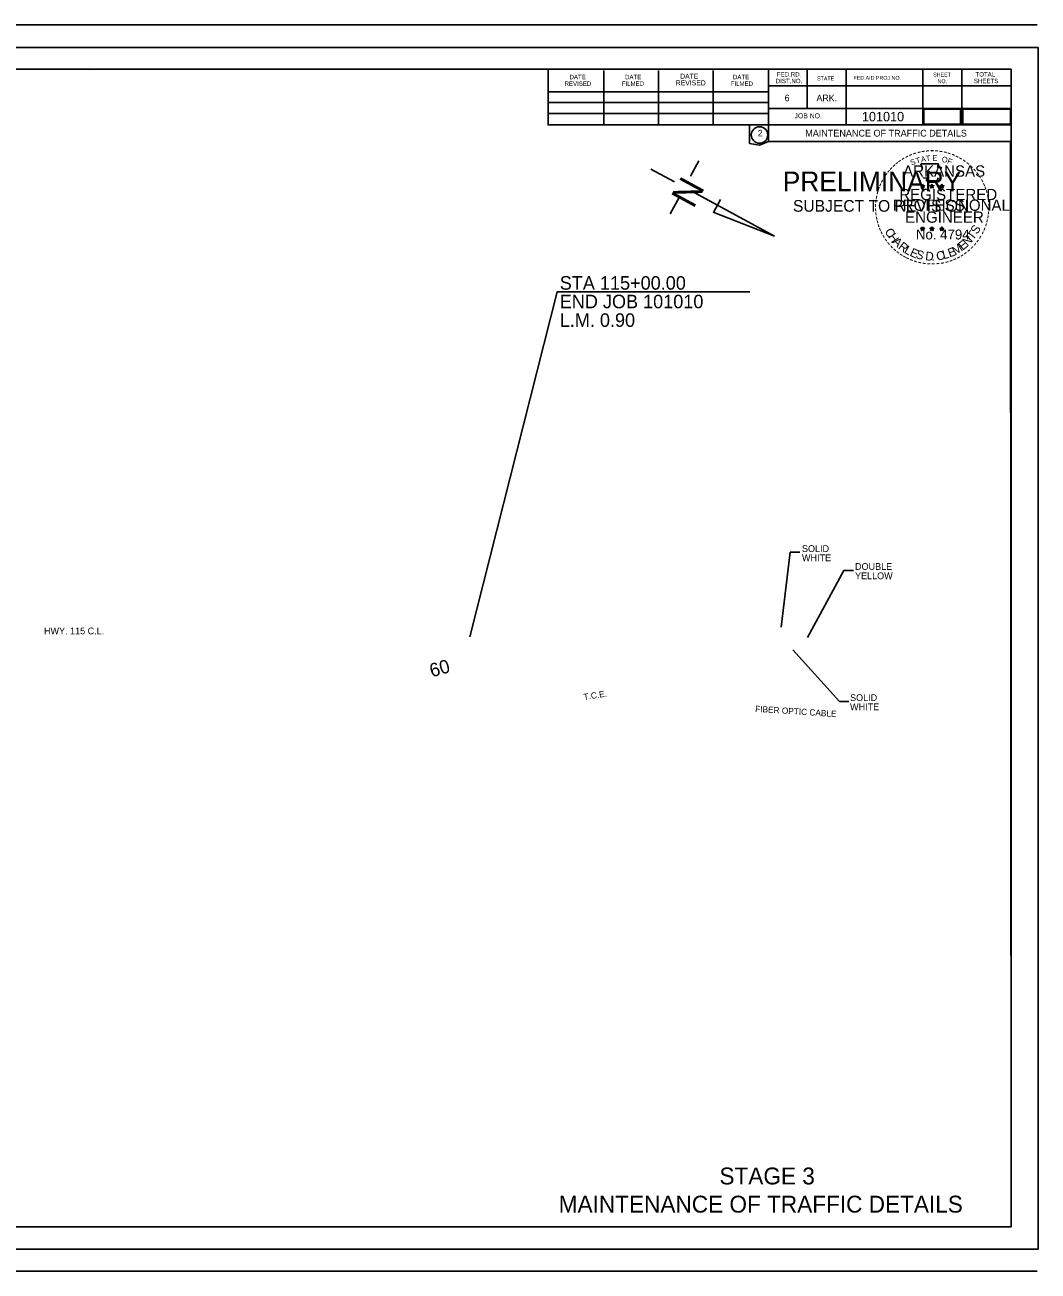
# Model space of a CAD drawing. Extents: x 9844 to 11605, y 9961 to 11312.
# Drawn here: x 10705 to 11605, y 9961 to 11067 of the extents above; entities that cross this region are included whole.
import ezdxf

# ---------------------------------------------------------------- set-up
doc = ezdxf.new("R2010")
doc.units = 0
for name, color, linetype in [('C-PSVP', 7, 'Continuous'), ('GREEN_TXT', 7, 'Continuous'), ('R_Border Notes', 7, 'Continuous'), ('R_Horz Alg', 7, 'Continuous'), ('R_Temp Const Easement Annot', 7, 'Continuous'), ('S_FIBER_OPTIC_CABLE_ANNOT', 7, 'Continuous'), ('SEAL-INFO', 7, 'Continuous'), ('SIGNATURE', 7, 'Continuous'), ('STA Text', 7, 'Continuous'), ('Stage 2', 7, 'Continuous'), ('TEXT', 7, 'Continuous'), ('Tracking', 7, 'Continuous'), ('White Markings DETOUR', 7, 'Continuous')]:
    doc.layers.add(name, color=color, linetype=linetype)

msp = doc.modelspace()

# ---------------------------------------------------------------- linework, layer by layer
for p, q in [((11303.5, 10946.1), (11296.1, 10932.5)), ((11260.8, 10938.8), (11281.8, 10927.4)), ((11299.2, 10918), (11370.7, 10879.2)), ((11285.8, 10913.6), (11278, 10899.1)), ((11322.6, 10911.7), (11316.4, 10900.3)), ((11370.7, 10879.2), (11316, 10900.6))]:
    msp.add_line(p, q)
at = {"layer": 'C-PSVP'}
for p, q in [((11500.3, 10924), (11502.1, 10923.5)), ((11500.3, 10924), (11501.6, 10923.8)), ((11500.3, 10924), (11501.5, 10923.4)), ((11501, 10922), (11502.1, 10923.5)), ((11501, 10922), (11501.6, 10923.2)), ((11501, 10922), (11502, 10923.1)), ((11502.1, 10925.3), (11501.8, 10924.1)), ((11503.1, 10922), (11502, 10923.1)), ((11502.1, 10923.5), (11502.1, 10925.3)), ((11502.1, 10925.3), (11502.3, 10924.1)), ((11503.8, 10924), (11502.1, 10923.5)), ((11503.1, 10922), (11502.1, 10923.5)), ((11503.8, 10924), (11502.4, 10923.8)), ((11503.1, 10922), (11502.4, 10923.5)), ((11503.8, 10924), (11502.8, 10923.5)), ((11508.7, 10924), (11510.4, 10923.5)), ((11508.7, 10924), (11509.9, 10923.8)), ((11508.7, 10924), (11509.8, 10923.4)), ((11509.3, 10922), (11510.4, 10923.5)), ((11509.3, 10922), (11510, 10923.2)), ((11509.3, 10922), (11510.4, 10923.1)), ((11510.4, 10925.3), (11510.2, 10924.1)), ((11510.4, 10923.5), (11510.4, 10925.3)), ((11510.4, 10925.3), (11510.6, 10924.1)), ((11512.1, 10924), (11510.4, 10923.5)), ((11511.5, 10922), (11510.4, 10923.5)), ((11511.5, 10922), (11510.4, 10923.1)), ((11512.1, 10924), (11510.7, 10923.8)), ((11511.5, 10922), (11510.8, 10923.5)), ((11512.1, 10924), (11511.1, 10923.5)), ((11517.5, 10924), (11519.2, 10923.4)), ((11517.5, 10924), (11518.7, 10923.8)), ((11517.5, 10924), (11518.7, 10923.4)), ((11518.1, 10921.9), (11519.2, 10923.4)), ((11518.1, 10921.9), (11518.8, 10923.2)), ((11518.1, 10921.9), (11519.2, 10923)), ((11519.2, 10925.3), (11519, 10924)), ((11519.2, 10923.4), (11519.2, 10925.3)), ((11519.2, 10925.3), (11519.5, 10924)), ((11521, 10924), (11519.2, 10923.4)), ((11520.3, 10921.9), (11519.2, 10923.4)), ((11520.3, 10921.9), (11519.2, 10923)), ((11521, 10924), (11519.5, 10923.7)), ((11520.3, 10921.9), (11519.6, 10923.4)), ((11521, 10924), (11519.9, 10923.5)), ((11500.3, 10886.2), (11502, 10885.6)), ((11500.3, 10886.2), (11501.6, 10886)), ((11500.3, 10886.2), (11501.5, 10885.6)), ((11501, 10884.1), (11502, 10885.6)), ((11501, 10884.1), (11501.6, 10885.4)), ((11501, 10884.1), (11502, 10885.2)), ((11502, 10887.4), (11501.8, 10886.2)), ((11502, 10885.6), (11502, 10887.4)), ((11502, 10887.4), (11502.3, 10886.2)), ((11503.8, 10886.2), (11502, 10885.6)), ((11503.1, 10884.1), (11502, 10885.6)), ((11503.1, 10884.1), (11502, 10885.2)), ((11503.8, 10886.2), (11502.3, 10885.9)), ((11503.1, 10884.1), (11502.4, 10885.6)), ((11503.8, 10886.2), (11502.7, 10885.7)), ((11508.6, 10886.2), (11510.4, 10885.6)), ((11508.6, 10886.2), (11509.9, 10886)), ((11508.6, 10886.2), (11509.8, 10885.6)), ((11509.3, 10884.1), (11510.4, 10885.6)), ((11509.3, 10884.1), (11509.9, 10885.4)), ((11509.3, 10884.1), (11510.4, 10885.2)), ((11510.4, 10887.4), (11510.2, 10886.2)), ((11510.4, 10885.6), (11510.4, 10887.4)), ((11510.4, 10887.4), (11510.6, 10886.2)), ((11512.1, 10886.2), (11510.4, 10885.6)), ((11511.4, 10884.1), (11510.4, 10885.6)), ((11511.4, 10884.1), (11510.4, 10885.2)), ((11512.1, 10886.2), (11510.7, 10885.9)), ((11511.4, 10884.1), (11510.8, 10885.6)), ((11512.1, 10886.2), (11511.1, 10885.7)), ((11517.5, 10886.1), (11519.2, 10885.6)), ((11517.5, 10886.1), (11518.7, 10885.9)), ((11517.5, 10886.1), (11518.7, 10885.5)), ((11518.1, 10884.1), (11519.2, 10885.6)), ((11518.1, 10884.1), (11518.8, 10885.3)), ((11518.1, 10884.1), (11519.2, 10885.2)), ((11519.2, 10887.4), (11519, 10886.1)), ((11519.2, 10885.6), (11519.2, 10887.4)), ((11519.2, 10887.4), (11519.5, 10886.1)), ((11520.9, 10886.1), (11519.2, 10885.6)), ((11520.3, 10884.1), (11519.2, 10885.6)), ((11520.3, 10884.1), (11519.2, 10885.2)), ((11520.9, 10886.1), (11519.5, 10885.9)), ((11520.3, 10884.1), (11519.6, 10885.5)), ((11520.9, 10886.1), (11519.9, 10885.6))]:
    msp.add_line(p, q, dxfattribs=at)
for points in [[(11500.5, 10943.4), (11501.9, 10939.3)], [(11518.1, 10938.8), (11518.8, 10940.2), (11515.4, 10940.1), (11516.1, 10943.4), (11500.5, 10943.4)], [(11503, 10931.3), (11503, 10930.9), (11505.8, 10930.8), (11505.5, 10928.4), (11514.9, 10928.4), (11515.9, 10931.1)], [(11502.1, 10925.3), (11503.1, 10922), (11500.3, 10924), (11503.8, 10924), (11501, 10922), (11502.1, 10925.3)], [(11510.4, 10925.3), (11511.5, 10922), (11508.7, 10924), (11512.1, 10924), (11509.3, 10922), (11510.4, 10925.3)], [(11519.2, 10925.3), (11520.3, 10921.9), (11517.5, 10924), (11521, 10924), (11518.1, 10921.9), (11519.2, 10925.3)], [(11502, 10887.4), (11503.1, 10884.1), (11500.3, 10886.2), (11503.8, 10886.2), (11501, 10884.1), (11502, 10887.4)], [(11510.4, 10887.4), (11511.4, 10884.1), (11508.6, 10886.2), (11512.1, 10886.2), (11509.3, 10884.1), (11510.4, 10887.4)], [(11519.2, 10887.4), (11520.3, 10884.1), (11517.5, 10886.1), (11520.9, 10886.1), (11518.1, 10884.1), (11519.2, 10887.4)]]:
    msp.add_lwpolyline(points, dxfattribs=at)
for centre, radius in [((11502, 10923.5), 0.861), ((11502, 10923.5), 0.723), ((11502, 10923.5), 0.579), ((11502, 10923.5), 0.495), ((11502, 10923.5), 0.374), ((11502, 10923.5), 0.248), ((11502, 10923.5), 0.148), ((11510.4, 10923.5), 0.861), ((11510.4, 10923.5), 0.723), ((11510.4, 10923.5), 0.579), ((11510.4, 10923.5), 0.495), ((11510.4, 10923.5), 0.374), ((11510.4, 10923.5), 0.248), ((11510.4, 10923.5), 0.148), ((11519.2, 10923.4), 0.861), ((11519.2, 10923.4), 0.723), ((11519.2, 10923.4), 0.579), ((11519.2, 10923.4), 0.495), ((11519.2, 10923.4), 0.374), ((11519.2, 10923.4), 0.248), ((11519.2, 10923.4), 0.148), ((11502, 10885.6), 0.861), ((11502, 10885.6), 0.723), ((11502, 10885.6), 0.579), ((11502, 10885.6), 0.495), ((11502, 10885.6), 0.374), ((11502, 10885.6), 0.248), ((11502, 10885.6), 0.148), ((11510.4, 10885.6), 0.861), ((11510.4, 10885.6), 0.723), ((11510.4, 10885.6), 0.579), ((11510.4, 10885.6), 0.495), ((11510.4, 10885.6), 0.374), ((11510.4, 10885.6), 0.248), ((11510.4, 10885.6), 0.148), ((11519.2, 10885.6), 0.861), ((11519.2, 10885.6), 0.723), ((11519.2, 10885.6), 0.579), ((11519.2, 10885.6), 0.495), ((11519.2, 10885.6), 0.374), ((11519.2, 10885.6), 0.248), ((11519.2, 10885.6), 0.148)]:
    msp.add_circle(centre, radius, dxfattribs=at)
at = {"layer": 'GREEN_TXT'}
for p, q in [((11603.9, 11066.7), (9843.9, 11066.7)), ((10000, 11027.3), (11580.9, 11027.3)), ((10762.6, 11026), (10762.6, 11026)), ((10762.6, 11026), (10762.6, 11026)), ((11169.6, 10977.9), (11169.6, 11027.3)), ((11218.9, 10977.9), (11218.9, 11026.3)), ((11267.7, 10977.9), (11267.7, 11026.3)), ((11316.1, 10977.9), (11316.1, 11026.3)), ((11365.4, 11027.3), (11365.4, 10963.3)), ((11399.6, 11027.3), (11399.6, 10992.6)), ((11434.3, 11027.3), (11434.3, 10977.9)), ((11502.2, 11027.3), (11502.2, 10977.9)), ((11536.9, 11027.3), (11536.9, 10977.9)), ((11580.9, 10000), (11580.9, 11027.3)), ((11169.6, 11007.2), (11365.4, 11007.2)), ((11580.9, 11012.6), (11365.4, 11012.6)), ((11580.9, 11012.7), (11580.9, 11012.7)), ((11169.6, 10997.9), (11365.4, 10997.9)), ((11169.6, 10988.2), (11365.4, 10988.2)), ((11580.9, 10992.6), (11365.4, 10992.6)), ((11580.9, 10977.9), (11169.6, 10977.9)), ((11365.4, 10963.3), (11580.9, 10963.3)), ((11580.9, 10000), (10000, 10000)), ((9843.9, 9960.6), (11603.9, 9960.6))]:
    msp.add_line(p, q, dxfattribs=at)
msp.add_circle((11357.3, 10969), 7.33, dxfattribs=at)
at = {"layer": 'R_Horz Alg'}
msp.add_lwpolyline([(11537.7, 10978.6), (11580.1, 10978.6), (11580.1, 10991.9), (11537.7, 10991.9)], close=True, dxfattribs=at)
at = {"layer": 'SEAL-INFO'}
for points in [[(9938, 11046.8), (11604.7, 11046.8), (11604.7, 9980.1), (9938, 9980.1)], [(10000, 10000), (11580.9, 10000), (11580.3, 10963.3), (11365.4, 10963.3), (11357.3, 10959.9), (11348.5, 10961.4), (11348.3, 10977.9), (11169.6, 10977.9), (11169.6, 11027.3), (10000, 11027.3)], [(10000, 10000), (11580.9, 10000), (11580.3, 10963.3), (11365.4, 10963.3), (11357.3, 10959.9), (11348.5, 10961.4), (11348.3, 10977.9), (11169.6, 10977.9), (11169.6, 11027.3), (10000, 11027.3)], [(10000, 10000), (11580.9, 10000), (11580.3, 10963.3), (11365.4, 10963.3), (11357.3, 10959.9), (11348.5, 10961.4), (11348.3, 10977.9), (11169.6, 10977.9), (11169.6, 11027.3), (10000, 11027.3)], [(10000, 10000), (11580.9, 10000), (11580.3, 10963.3), (11365.4, 10963.3), (11357.3, 10959.9), (11348.5, 10961.4), (11348.3, 10977.9), (11169.6, 10977.9), (11169.6, 11027.3), (10000, 11027.3)]]:
    msp.add_lwpolyline(points, close=True, dxfattribs=at)
at = {"layer": 'STA Text'}
msp.add_lwpolyline([(11348.8, 10829.8), (11177.7, 10829.8), (11100, 10523.5)], dxfattribs=at)
at = {"layer": 'Stage 2'}
for points in [[(11393, 10598.7), (11384.6, 10598.7), (11376.4, 10532.1)], [(11440.7, 10582.5), (11432.3, 10582.5), (11400, 10523)], [(11387, 10512.1), (11428.3, 10466.3), (11436.6, 10466.3)]]:
    msp.add_lwpolyline(points, dxfattribs=at)
at = {"layer": 'White Markings DETOUR'}
msp.add_lwpolyline([(11503.2, 10978.6), (11535.9, 10978.6), (11535.9, 10991.9), (11503.2, 10991.9)], close=True, dxfattribs=at)

# ---------------------------------------------------------------- texts
msp.add_text('N', height=23.3, rotation=241.4896).set_placement((11288.7, 10933.8))
at = {"layer": 'C-PSVP'}
for s, height, rotation, p in [('-', 8, 28.7918, (11487.9, 10946.1)), ('-', 8, 24.3072, (11491.1, 10947.7)), ('-', 8, 19.1761, (11494.3, 10949.1)), ('-', 8, 13.6302, (11498, 10950.3)), ('-', 8, 10.2193, (11501.4, 10951.1)), ('T', 5, 6.0228, (11505.2, 10945.6)), ('-', 8, 5.8968, (11505, 10951.6)), ('-', 8, 0.1862, (11508.9, 10952)), ('E', 5, 0.8323, (11510.8, 10946.1)), ('-', 8, 357.743, (11512.5, 10951.9)), ('-', 8, 352.1617, (11516.2, 10951.6)), ('-', 8, 347.2049, (11519.8, 10951.1)), ('-', 8, 342.3362, (11523, 10950.3)), ('-', 8, 337.8551, (11526.7, 10949.2)), ('-', 8, 334.1211, (11529.8, 10947.8)), ('-', 8, 48.4231, (11475.3, 10935.9)), ('-', 8, 42.9622, (11477.5, 10938.3)), ('-', 8, 38.9507, (11479.7, 10940.4)), ('-', 8, 36.2317, (11482, 10942.3)), ('-', 8, 34.0636, (11484.9, 10944.3)), ('S', 5, 21.594, (11492.3, 10941.8)), ('T', 5, 16.4036, (11496.9, 10943.5)), ('A', 5, 11.2132, (11501, 10944.7)), ('O', 5, 350.4515, (11518.8, 10945.1)), ('F', 5, 340.0707, (11523.5, 10943.9)), ('-', 8, 329.6409, (11532.7, 10946.4)), ('-', 8, 325.8627, (11535.9, 10944.6)), ('-', 8, 320.5297, (11539, 10942.5)), ('-', 8, 315.5786, (11542, 10940)), ('-', 8, 62.8713, (11468, 10925)), ('-', 8, 58.0706, (11469.6, 10928)), ('-', 8, 54.2325, (11471.2, 10930.7)), ('-', 8, 50.6142, (11473.2, 10933.5)), ('-', 8, 309.8797, (11544.8, 10937.3)), ('-', 8, 306.6522, (11547.5, 10934.3)), ('-', 7, 303.6753, (11549.9, 10931.4)), ('-', 8, 299.6684, (11551.5, 10928.4)), ('-', 8, 75.461, (11464.6, 10915.2)), ('-', 8, 72.3945, (11465.6, 10918.8)), ('-', 8, 67.7743, (11466.7, 10921.9)), ('-', 8, 294.6628, (11553.1, 10925.3)), ('-', 8, 290.5728, (11554.4, 10922.5)), ('-', 8, 285.1233, (11555.6, 10919.6)), ('-', 8, 89.0622, (11463.4, 10904.7)), ('-', 8, 85.1863, (11463.6, 10908.2)), ('-', 8, 81.2013, (11464, 10911.6)), ('-', 8, 280.5493, (11556.6, 10915.9)), ('-', 8, 276.5962, (11557.4, 10912)), ('-', 8, 274.3301, (11557.7, 10908.4)), ('-', 8, 94.1959, (11463.6, 10901.1)), ('-', 8, 98.9479, (11464, 10897.7)), ('-', 8, 101.7149, (11464.7, 10894.1)), ('-', 8, 260.9953, (11557.4, 10898.6)), ('-', 8, 263.5172, (11557.7, 10901.9)), ('-', 8, 269.9407, (11557.8, 10905.2)), ('-', 8, 105.4578, (11465.5, 10891.1)), ('-', 8, 109.0874, (11466.5, 10887.9)), ('-', 8, 114.0643, (11467.8, 10884.9)), ('C', 7.7, 296.9133, (11468.2, 10883.9)), ('T', 7.7, 51.5114, (11546.8, 10875.1)), ('S', 7.7, 57.878, (11550.5, 10880.3)), ('-', 8, 247.8887, (11554.8, 10888.3)), ('-', 8, 255.7626, (11555.9, 10891.8)), ('-', 8, 255.7626, (11556.8, 10895.3)), ('-', 8, 115.7289, (11469.3, 10881.9)), ('-', 8, 120.4471, (11471.1, 10878.9)), ('-', 8, 125.8934, (11473.1, 10876.1)), ('-', 8, 130.7181, (11475.4, 10873.4)), ('H', 7.7, 303.2799, (11471.1, 10878.7)), ('A', 7.7, 316.013, (11474.8, 10873.6)), ('R', 7.7, 322.3796, (11479.9, 10868.7)), ('E', 7.7, 38.7783, (11537.6, 10866.2)), ('N', 7.7, 45.1449, (11542, 10869.9)), ('-', 8, 231.2538, (11547.4, 10875.3)), ('-', 8, 233.8452, (11549.5, 10878.1)), ('-', 8, 239.0712, (11551.5, 10881.4)), ('-', 8, 244.6197, (11553.5, 10885.1)), ('-', 8, 134.2238, (11478, 10870.6)), ('-', 8, 138.9338, (11480.7, 10868.3)), ('-', 8, 144.6463, (11483.4, 10866.3)), ('-', 8, 148.0898, (11486.2, 10864.4)), ('-', 8, 151.5704, (11489.1, 10862.8)), ('L', 7.7, 328.7461, (11485, 10864.9)), ('E', 7.7, 335.1127, (11490.1, 10862.1)), ('S', 7.7, 341.4792, (11495.4, 10860)), ('D', 7.7, 354.2124, (11504.2, 10857.9)), ('C', 7.7, 6.9455, (11514.7, 10857.7)), ('L', 7.7, 13.3121, (11520.6, 10858.7)), ('E', 7.7, 19.6786, (11526.1, 10860.3)), ('M', 7.7, 32.4117, (11531.2, 10862.1)), ('-', 8, 212.2491, (11537, 10865.6)), ('-', 8, 215.7363, (11539.6, 10867.6)), ('-', 8, 221.0851, (11542.4, 10869.9)), ('-', 8, 225.7653, (11545, 10872.5)), ('-', 8, 154.6002, (11491.7, 10861.6)), ('-', 8, 158.5612, (11494.9, 10860.3)), ('-', 8, 162.7983, (11498.3, 10859.2)), ('-', 8, 167.5555, (11501.9, 10858.4)), ('-', 8, 173.1155, (11505.7, 10857.9)), ('-', 8, 176.5183, (11509.5, 10857.6)), ('-', 8, 181.5918, (11513.2, 10857.7)), ('.', 7.7, 0.5789, (11510.1, 10857.5)), ('-', 8, 185.8167, (11517.2, 10858.1)), ('-', 8, 191.2858, (11520.9, 10858.7)), ('-', 8, 195.4743, (11524.6, 10859.7)), ('-', 8, 200.7184, (11528, 10860.9)), ('-', 8, 204.2516, (11531, 10862.3)), ('-', 8, 207.3568, (11534.2, 10863.9))]:
    msp.add_text(s, height=height, rotation=rotation, dxfattribs=at).set_placement(p)
for s, height, p in [('ARKANSAS', 10, (11484.8, 10932)), ('REGISTERED', 10, (11481.4, 10911.2)), ('PROFESSIONAL', 10, (11475.6, 10901.7)), ('ENGINEER', 10, (11486.6, 10891.1)), ('No. 4794', 8.78, (11496.2, 10876.3))]:
    msp.add_text(s, height=height, dxfattribs=at).set_placement(p)
at = {"layer": 'GREEN_TXT'}
for s, height, p in [('DATE', 3.91, (11188.6, 11018.5)), ('DATE', 3.91, (11237.9, 11018.5)), ('REVISED', 4.4, (11282.9, 11013.1)), ('DATE', 4.4, (11286.8, 11019)), ('DATE', 3.91, (11333.7, 11018.5)), ('DIST.NO.', 3.91, (11371.8, 11015)), ('FED.RD.', 3.91, (11372.8, 11020.9)), ('STATE', 3.42, (11408.4, 11017.5)), ('FED.AID PROJ.NO.', 3.42, (11440.7, 11018)), ('SHEET', 3.42, (11511.5, 11020.9)), ('NO.', 3.42, (11515.4, 11015)), ('SHEETS', 3.91, (11547.7, 11015)), ('TOTAL', 3.91, (11549.1, 11020.9)), ('REVISED', 3.91, (11184.2, 11012.6)), ('FILMED', 3.91, (11235, 11012.6)), ('FILMED', 3.91, (11331.7, 11012.6)), ('6', 5.86, (11379.6, 10998.9)), ('ARK.', 5.86, (11407.9, 10998.9)), ('JOB NO.', 4.4, (11388.4, 10983.8)), ('2', 5.86, (11355.7, 10967.7)), ('STAGE 3 ', 15, (11321.7, 10037.5)), ('MAINTENANCE OF TRAFFIC DETAILS', 15, (11179, 10012.5))]:
    msp.add_text(s, height=height, dxfattribs=at).set_placement(p)
at = {"layer": 'R_Border Notes'}
for s, height, p in [('101010', 8.4, (11448.2, 10981.1)), ('MAINTENANCE OF TRAFFIC DETAILS', 6, (11397.9, 10967.6))]:
    msp.add_text(s, height=height, dxfattribs=at).set_placement(p)
at = {"layer": 'R_Temp Const Easement Annot'}
msp.add_text('T.C.E.', height=5.5, rotation=8.9375, dxfattribs=at).set_placement((11201.5, 10467.4))
at = {"layer": 'S_FIBER_OPTIC_CABLE_ANNOT'}
msp.add_text('FIBER OPTIC CABLE', height=5.5, rotation=356.3184, dxfattribs=at).set_placement((11353.3, 10457))
at = {"layer": 'SIGNATURE'}
for s, height, p in [('PRELIMINARY', 17.5, (11377.9, 10919)), ('SUBJECT TO REVISION', 10.376, (11387, 10900.9))]:
    msp.add_text(s, height=height, dxfattribs=at).set_placement(p)
at = {"layer": 'STA Text'}
for s, p in [('STA 115+00.00', (11179.9, 10831.7)), ('END JOB 101010', (11179.9, 10815.2)), ('L.M. 0.90', (11179.9, 10798.7))]:
    msp.add_text(s, height=12, dxfattribs=at).set_placement(p)
at = {"layer": 'Stage 2'}
for s, p in [('WHITE', (11395, 10590.7)), ('SOLID', (11395, 10598.9)), ('DOUBLE', (11442.1, 10583)), ('YELLOW', (11442.1, 10574.7)), ('WHITE', (11437.7, 10458.4)), ('SOLID', (11437.7, 10466.6))]:
    msp.add_text(s, height=6, rotation=360, dxfattribs=at).set_placement(p)
at = {"layer": 'TEXT'}
msp.add_text('HWY. 115 C.L.', height=6, rotation=360, dxfattribs=at).set_placement((10721.9, 10525.8))
at = {"layer": 'Tracking'}
msp.add_text('60', height=12, rotation=16.1937, dxfattribs=at).set_placement((11066.3, 10487.5))

doc.saveas('drawing.dxf')
